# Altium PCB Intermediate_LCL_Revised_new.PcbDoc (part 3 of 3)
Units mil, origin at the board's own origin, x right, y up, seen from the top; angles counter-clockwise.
Board outline 12850 x 6950 mil, 4 copper layers (Top Layer, Lay1, gnd, Bottom Layer), stack 23.756 mil thick; 473 components, 243 nets, 1278 pads, 73 vias.
Unrouted connection lines stored in the file: 289.
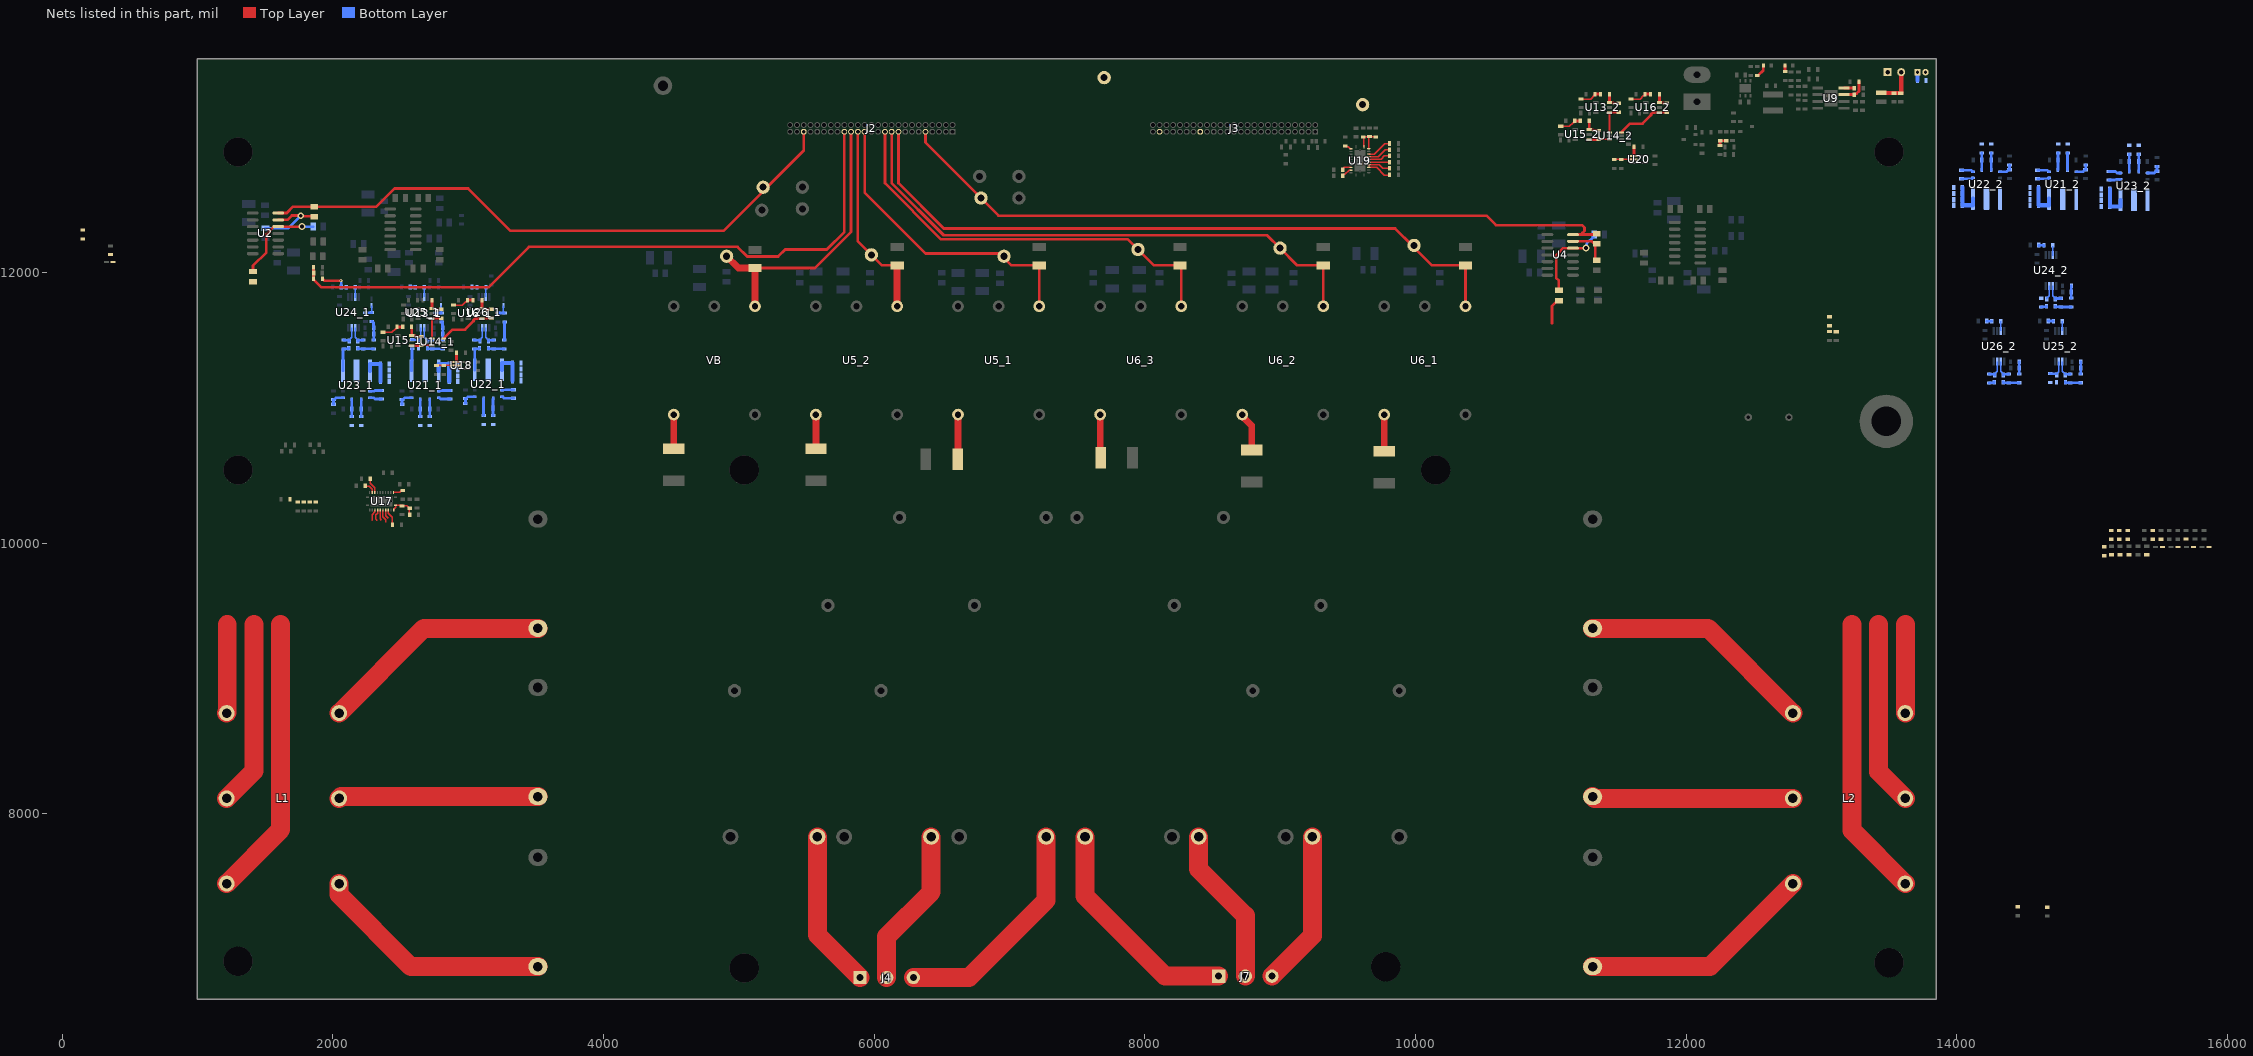
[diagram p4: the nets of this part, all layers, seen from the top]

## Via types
v1: diameter 50, hole 28, Top Layer to Bottom Layer, 40 vias
v2: diameter 20, hole 12, Top Layer to Bottom Layer, 29 vias
v3: diameter 40, hole 20, Top Layer to Bottom Layer, 4 vias

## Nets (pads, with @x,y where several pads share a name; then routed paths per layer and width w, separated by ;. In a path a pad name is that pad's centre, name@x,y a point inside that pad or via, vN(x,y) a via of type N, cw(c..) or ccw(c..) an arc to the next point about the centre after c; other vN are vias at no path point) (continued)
NetC56_2_1: C56_2.1 R57_2.1 R58_2.2 | length 162.2
  Top Layer w10: C56_2.1@11224,13281.21 11294.67,13281.21 11327,13313.54 R57_2.1@11327,13318.46
  Top Layer w20: R57_2.1@11327,13318.46 R58_2.2@11367.89,13318.46
NetC59_1_1: C59_1.1 R60_1.1 R61_1.2 | length 162.7
  Top Layer w10: C59_1.1@2372.51,11558.99 2437,11558.99 2463.77,11585.76 2468.7,11585.76 2475.51,11592.57 R60_1.1@2475.51,11597.49
  Top Layer w20: R60_1.1@2475.51,11597.49 R61_1.2@2516.4,11597.49
NetC59_2_1: C59_2.1 R60_2.1 R61_2.2 | length 162.7
  Top Layer w10: C59_2.1@11074,13081.21 11138.49,13081.21 11165.26,13107.98 11170.19,13107.98 11177,13114.79 R60_2.1@11177,13119.71
  Top Layer w20: R60_2.1@11177,13119.71 R61_2.2@11217.89,13119.71
NetC61_1_1: C61_1.1 R63_1.1 R64_1.2 | length 162.2
  Top Layer w10: C61_1.1@2892.51,11758.99 2958.25,11758.99 2983.77,11784.51 2988.7,11784.51 2995.51,11791.32 R63_1.1@2995.51,11796.24
  Top Layer w20: R63_1.1@2995.51,11796.24 R64_1.2@3036.4,11796.24
NetC61_2_1: C61_2.1 R63_2.1 R64_2.2 | length 162.2
  Top Layer w10: C61_2.1@11594,13281.21 11659.74,13281.21 11685.26,13306.72 11690.19,13306.72 11697,13313.54 R63_2.1@11697,13318.46
  Top Layer w20: R63_2.1@11697,13318.46 R64_2.2@11737.89,13318.46
NetC63_1: C63.1 R66.1 R67.1 U17.23 U17.24 | length 203.7
  Top Layer w10: U17.23@2449.57,10244.53 2449.57,10251.06 2464.33,10265.83 U17.24@2464.33,10278.98 ; U17.24@2464.33,10279.96 2464.61,10279.68 2512.99,10279.68 2515.96,10276.72 2547.69,10276.72 2557.13,10267.28 2557.13,10264.4 2563.94,10257.59 R66.1@2568.86,10257.59 2565.29,10254.02 R67.1@2565.29,10211.4
NetC75_1: C75.1 R100.1 R101.1 U19.23 U19.24 | length 250.2
  Top Layer w10: R100.1@9615.24,13001.28 R100.1@9619.53,13001.28 ; U19.24@9619.53,12929.53 R100.1@9619.53,13001.28 ; U19.23@9654.96,12916.1 9654.96,12995.57 C75.1@9660.68,13001.28 ; R101.1@9706.15,13001.28 C75.1@9660.68,13001.28 ; R100.1@9619.53,13001.28 C75.1@9660.68,13001.28
NetC88_1_2: C88_1.2 R124_1.1 U21_1.6 | length 110.7
  Bottom Layer w20: R124_1.1@2512.06,11026.24 C88_1.2@2512.06,11061.74 2518.95,11061.74 2532.49,11075.29 U21_1.6@2581.67,11075.29
NetC88_2_2: C88_2.2 R124_2.1 U21_2.6 | length 110.7
  Bottom Layer w20: U21_2.6@14883.49,12744.95 14932.66,12744.95 14946.2,12758.5 C88_2.2@14953.09,12758.5 R124_2.1@14953.09,12794
NetC89_1_1: C89_1.1 U21_1.2 | length 86.6
  Bottom Layer w20: U21_1.2@2782.45,11122.53 2786.08,11122.53 2791.05,11127.5 C89_1.1@2867.02,11127.5
NetC89_1_2: C89_1.2 U21_1.3 | length 89
  Bottom Layer w20: U21_1.3@2782.45,11075.29 2786.08,11075.29 2796.85,11064.51 C89_1.2@2867.02,11064.51
NetC89_2_1: C89_2.1 U21_2.2 | length 86.6
  Bottom Layer w20: C89_2.1@14598.13,12692.74 14674.11,12692.74 14679.08,12697.71 U21_2.2@14682.7,12697.71
NetC89_2_2: C89_2.2 U21_2.3 | length 89
  Bottom Layer w20: C89_2.2@14598.13,12755.73 14668.3,12755.73 14679.08,12744.95 U21_2.3@14682.7,12744.95
NetC90_1_1: C90_1.1 R125_1.1 U21_1.4 | length 127.5
  Bottom Layer w20: R125_1.1@2716.39,10936.39 2716.39,11058.75 2717.49,11059.85 U21_1.4@2717.49,11063.48
NetC90_2_1: C90_2.1 R125_2.1 U21_2.4 | length 127.5
  Bottom Layer w20: U21_2.4@14747.66,12756.76 14747.66,12760.39 14748.77,12761.49 R125_2.1@14748.77,12883.85
NetC91_1_1: C91_1.1 R126_1.1 U21_1.5 | length 127.3
  Bottom Layer w20: R126_1.1@2646.17,10936.39 2646.17,11059.39 2646.63,11059.85 U21_1.5@2646.63,11063.48
NetC91_2_1: C91_2.1 R126_2.1 U21_2.5 | length 127.3
  Bottom Layer w20: U21_2.5@14818.53,12756.76 14818.53,12760.39 14818.99,12760.85 R126_2.1@14818.99,12883.85
NetC96_1_2: C96_1.2 R127_1.1 U22_1.6 | length 110.7
  Bottom Layer w20: R127_1.1@2980,11032.92 C96_1.2@2980,11068.43 2986.89,11068.43 3000.43,11081.97 U22_1.6@3049.61,11081.97
NetC96_2_2: C96_2.2 R127_2.1 U22_2.6 | length 110.7
  Bottom Layer w20: U22_2.6@14320.39,12744.95 14369.57,12744.95 14383.11,12758.5 C96_2.2@14390,12758.5 R127_2.1@14390,12794
NetC97_1_1: C97_1.1 U22_1.2 | length 86.6
  Bottom Layer w20: U22_1.2@3250.39,11129.21 3254.02,11129.21 3258.99,11134.18 C97_1.1@3334.96,11134.18
NetC97_1_2: C97_1.2 U22_1.3 | length 89
  Bottom Layer w20: U22_1.3@3250.39,11081.97 3254.02,11081.97 3264.79,11071.19 C97_1.2@3334.96,11071.19
NetC97_2_1: C97_2.1 U22_2.2 | length 86.6
  Bottom Layer w20: C97_2.1@14035.04,12692.74 14111.01,12692.74 14115.98,12697.71 U22_2.2@14119.61,12697.71
NetC97_2_2: C97_2.2 U22_2.3 | length 89
  Bottom Layer w20: C97_2.2@14035.04,12755.73 14105.21,12755.73 14115.98,12744.95 U22_2.3@14119.61,12744.95
NetC98_1_1: C98_1.1 R128_1.1 U22_1.4 | length 127.5
  Bottom Layer w20: R128_1.1@3184.32,10943.07 3184.32,11065.43 3185.43,11066.54 U22_1.4@3185.43,11070.16
NetC98_2_1: C98_2.1 R128_2.1 U22_2.4 | length 127.5
  Bottom Layer w20: U22_2.4@14184.57,12756.76 14184.57,12760.39 14185.68,12761.49 R128_2.1@14185.68,12883.85
NetC99_1_1: C99_1.1 R129_1.1 U22_1.5 | length 127.3
  Bottom Layer w20: R129_1.1@3114.11,10943.07 3114.11,11066.07 3114.57,11066.54 U22_1.5@3114.57,11070.16
NetC99_2_1: C99_2.1 R129_2.1 U22_2.5 | length 127.3
  Bottom Layer w20: U22_2.5@14255.43,12756.76 14255.43,12760.39 14255.89,12760.85 R129_2.1@14255.89,12883.85
NetC104_1_2: C104_1.2 R130_1.1 U23_1.6 | length 110.7
  Bottom Layer w20: R130_1.1@2005.15,11026.24 C104_1.2@2005.15,11061.74 2012.04,11061.74 2025.59,11075.29 U23_1.6@2074.76,11075.29
NetC104_2_2: C104_2.2 R130_2.1 U23_2.6 | length 110.7
  Bottom Layer w20: U23_2.6@15410.39,12734.95 15459.57,12734.95 15473.11,12748.5 C104_2.2@15480,12748.5 R130_2.1@15480,12784
NetC105_1_1: C105_1.1 U23_1.2 | length 86.6
  Bottom Layer w20: U23_1.2@2275.55,11122.53 2275.7,11122.69 2306.6,11122.69 2311.41,11127.5 C105_1.1@2360.12,11127.5
NetC105_1_2: C105_1.2 U23_1.3 | length 89
  Bottom Layer w20: U23_1.3@2275.55,11075.29 2275.7,11075.13 2300.79,11075.13 2311.41,11064.51 C105_1.2@2360.12,11064.51
NetC105_2_1: C105_2.1 U23_2.2 | length 86.6
  Bottom Layer w20: C105_2.1@15125.04,12682.74 15173.74,12682.74 15178.55,12687.55 15209.45,12687.55 U23_2.2@15209.61,12687.71
NetC105_2_2: C105_2.2 U23_2.3 | length 89
  Bottom Layer w20: C105_2.2@15125.04,12745.73 15173.74,12745.73 15184.36,12735.11 15209.45,12735.11 U23_2.3@15209.61,12734.95
NetC106_1_1: C106_1.1 R131_1.1 U23_1.4 | length 127.5
  Bottom Layer w20: R131_1.1@2209.48,10936.39 2210.43,10937.34 2210.43,11063.32 U23_1.4@2210.59,11063.48
NetC106_2_1: C106_2.1 R131_2.1 U23_2.4 | length 127.5
  Bottom Layer w20: U23_2.4@15274.57,12746.76 15274.72,12746.92 15274.72,12872.9 R131_2.1@15275.68,12873.85
NetC107_1_1: C107_1.1 R132_1.1 U23_1.5 | length 127.3
  Bottom Layer w20: R132_1.1@2139.26,10936.39 2139.56,10936.69 2139.56,11063.32 U23_1.5@2139.72,11063.48
NetC107_2_1: C107_2.1 R132_2.1 U23_2.5 | length 127.3
  Bottom Layer w20: U23_2.5@15345.43,12746.76 15345.59,12746.92 15345.59,12873.55 R132_2.1@15345.89,12873.85
NetC109_1_1: C109_1.1 R136_1.2 U24_1.2 | length 144.7
  Bottom Layer w10: U24_1.2@2165.8,11591.65 2165.8,11519.63 C109_1.1@2184.5,11500.93
  Bottom Layer w20: C109_1.1@2184.5,11494.04 2184.5,11497.61 2186.31,11499.42 2223.83,11499.42 R136_1.2@2225.64,11501.24
NetC109_1_2: C109_1.2 R135_1.2 U24_1.3 | length 144.3
  Bottom Layer w10: C109_1.2@2121.5,11500.93 2140.2,11519.63 U24_1.3@2140.2,11591.65
  Bottom Layer w20: R135_1.2@2080.45,11500.93 2082.26,11499.11 2119.69,11499.11 2121.5,11497.3 C109_1.2@2121.5,11494.04
NetC109_2_1: C109_2.1 R136_2.2 U24_2.2 | length 144.7
  Bottom Layer w10: U24_2.2@14710.03,11900.72 14710.03,11828.7 C109_2.1@14728.73,11810
  Bottom Layer w20: C109_2.1@14728.73,11803.11 14728.73,11806.69 14730.54,11808.5 14768.06,11808.5 R136_2.2@14769.87,11810.31
NetC109_2_2: C109_2.2 R135_2.2 U24_2.3 | length 105.4
  Bottom Layer w10: C109_2.2@14665.74,11803.11 14665.74,11810 14684.44,11828.7 U24_2.3@14684.44,11900.72
NetC113_1_1: C113_1.1 R142_1.2 U25_1.2 | length 143.8
  Bottom Layer w10: U25_1.2@2675.8,11591.65 2675.8,11522.4 2697.26,11500.93 C113_1.1@2697.26,11494.04
  Bottom Layer w20: C113_1.1@2699.08,11499.42 2733.83,11499.42 R142_1.2@2735.64,11501.24
NetC113_1_2: C113_1.2 R141_1.2 U25_1.3 | length 151.7
  Bottom Layer w10: C113_1.2@2634.27,11494.04 2634.27,11500.93 2650.2,11516.86 U25_1.3@2650.2,11591.65
  Bottom Layer w20: R141_1.2@2585.77,11503.93 2587.58,11502.11 C113_1.2@2632.46,11502.11
NetC113_2_1: C113_2.1 R142_2.2 U25_2.2 | length 143.8
  Bottom Layer w10: U25_2.2@14780.03,11340.72 14780.03,11271.47 14801.5,11250 C113_2.1@14801.5,11243.11
  Bottom Layer w20: C113_2.1@14803.31,11248.5 14838.06,11248.5 R142_2.2@14839.87,11250.31
NetC113_2_2: C113_2.2 R141_2.2 U25_2.3 | length 151.7
  Bottom Layer w10: C113_2.2@14738.5,11243.11 14738.5,11250 14754.44,11265.93 U25_2.3@14754.44,11340.72
  Bottom Layer w20: R141_2.2@14690,11253 14691.81,11251.19 C113_2.2@14736.69,11251.19
NetC117_1_1: C117_1.1 R148_1.2 U26_1.2 | length 144.7
  Bottom Layer w10: U26_1.2@3131.12,11591.65 3131.12,11519.63 C117_1.1@3149.82,11500.93
  Bottom Layer w20: C117_1.1@3149.82,11494.04 3149.82,11497.61 3151.63,11499.42 3189.15,11499.42 R148_1.2@3190.96,11501.24
NetC117_1_2: C117_1.2 R147_1.2 U26_1.3 | length 144.3
  Bottom Layer w10: C117_1.2@3086.82,11500.93 3105.53,11519.63 U26_1.3@3105.53,11591.65
  Bottom Layer w20: R147_1.2@3045.77,11500.93 3047.58,11499.11 3085.01,11499.11 3086.82,11497.3 C117_1.2@3086.82,11494.04
NetC117_2_1: C117_2.1 R148_2.2 U26_2.2 | length 144.7
  Bottom Layer w10: U26_2.2@14325.35,11340.72 14325.35,11268.7 C117_2.1@14344.05,11250
  Bottom Layer w20: C117_2.1@14344.05,11243.11 14344.05,11246.69 14345.86,11248.5 14383.38,11248.5 R148_2.2@14385.19,11250.31
NetC117_2_2: C117_2.2 R147_2.2 U26_2.3 | length 144.3
  Bottom Layer w10: C117_2.2@14281.06,11250 14299.76,11268.7 U26_2.3@14299.76,11340.72
  Bottom Layer w20: R147_2.2@14240,11250 14241.81,11248.19 14279.24,11248.19 14281.06,11246.38 C117_2.2@14281.06,11243.11
NetDS1_1: DS1.1 R29.1 | length 45
  Top Layer w20: R29.1@12731.2,13485.15 12731.33,13485.28 12731.33,13529.87 DS1.1@12731.46,13530
NetDS2_1: DS2.1 R43.1 | length 96.2
  Top Layer w20: R43.1@12527.45,13455.58 12532.37,13455.58 12571.15,13494.35 12571.15,13528.19 DS2.1@12572.96,13530
NetR2_2: R2.2 R4.2 U2.6 | length 581.1
  Top Layer w20: U2.6@1597.09,12388.86 1665.18,12388.86 1697.3,12420.98 1760.48,12420.98 1766.3,12415.16 1858.9,12415.16 R2.2@1862.6,12411.46
  Bottom Layer w20: R4.2@1502.6,12326.26 1670,12326.26 v1(1762.6,12418.86)
NetR5_2: R5.2 R6.1 U2.5 | length 700.5
  Top Layer w20: R5.2@1410,12000.56 1410,12050 1508.84,12148.84 1508.84,12282.11 1565.59,12338.86 U2.5@1597.09,12338.86 v1(1772.6,12338.86)
  Bottom Layer w20: v1@1772.6,12346.98 v1(1772.6,12338.86) R6.1@1855.2,12338.86
NetR8_2: R8.2 R10.2 U4.6 | length 300.2
  Top Layer w20: U4.6@11164.49,12230 11303.74,12230 11321.14,12212.6 11330,12212.6 11330,12090 R10.2@11326.54,12093.46
NetR11_2: R11.2 R12.1 U4.5 | length 636.8
  Top Layer w20: R11.2@11060,11867.4 11060,11940.56 11040,11960.56 11040,12125.58 11068.82,12154.4 11068.82,12157.64 11091.18,12180 v1(11260,12180)
  Bottom Layer w20: v1(11260,12180) 11265.74,12185.74 11265.74,12214.28 11322.6,12271.14 R12.1@11322.6,12280
NetR13_1_2: R13_1.2 U5_1.5 | length 330.8
  Top Layer w50: R13_1.2@6618.11,10620 6619.06,10620.94 6619.06,10949.06 U5_1.5@6620,10950
NetR13_2_2: R13_2.2 U5_2.5 | length 231.9
  Top Layer w50: R13_2.2@5570,10718.11 U5_2.5@5570,10950
NetR13_3_2: R13_3.2 VB.5 | length 247.2
  Top Layer w50: R13_3.2@4520,10702.76 VB.5@4520,10950
NetR15_1_2: R15_1.2 U6_1.5 | length 271.9
  Top Layer w50: R15_1.2@9770,10678.11 U6_1.5@9770,10950
NetR15_2_2: R15_2.2 U6_2.5 | length 290.9
  Top Layer w50: U6_2.5@8720,10950 8720,10940.09 8790,10870.09 R15_2.2@8790,10688.11
NetR15_3_2: R15_3.2 U6_3.5 | length 321.6
  Top Layer w50: U6_3.5@7670,10950 7671.89,10948.11 7671.89,10631.89 R15_3.2@7673.78,10630
NetR34_2: R34.2 U9.4 | length 77
  Top Layer w20: U9.4@13167,13364 13239.44,13364 13241.65,13361.79 R34.2@13243.11,13361.79
NetR36_2: R36.2 R38.2 U9.3 | length 195.9
  Top Layer w20: U9.3@13167,13314 13167.5,13314.5 13242.83,13314.5 R36.2@13243.41,13315.08 13243.41,13320 13245.22,13321.81 13259.95,13321.81 13277.3,13339.15 13277.3,13410.35 R38.2@13278.08,13411.14
NetR58_1_1: R58_1.1 R59_1.2 U13_1.3 | length 134.4
  Top Layer w20: R58_1.1@2732.4,11796.24 2732.45,11796.19 U13_1.3@2732.51,11734.89 U13_1.3@2732.51,11734.89 2734.32,11733.08 2756.7,11733.08 2761.78,11728 R59_1.2@2802.67,11728
NetR58_2_1: R58_2.1 R59_2.2 U13_2.3 | length 134.4
  Top Layer w20: R58_2.1@11433.89,13318.46 11433.94,13318.4 11433.94,13257.16 U13_2.3@11434,13257.11 11435.81,13255.3 11458.19,13255.3 11463.27,13250.22 R59_2.2@11504.16,13250.22
NetR59_1_1: R59_1.1 U13_1.1 U14_1.1 | length 217.5
  Top Layer w10: U14_1.1@2733.46,11513.65 U14_1.1@2733.81,11513.31 ; R59_1.1@2801.72,11661.05 R59_1.1@2802.67,11662
  Top Layer w15: U14_1.1@2733.46,11513.65 U13_1.1@2733.46,11661.05
  Top Layer w20: U13_1.1@2733.46,11661.05 R59_1.1@2801.72,11661.05
NetR59_2_1: R59_2.1 U13_2.1 U14_2.1 | length 217.5
  Top Layer w10: U14_2.1@11434.95,13035.87 U14_2.1@11435.3,13035.52 ; R59_2.1@11503.21,13183.26 R59_2.1@11504.16,13184.22
  Top Layer w15: U14_2.1@11434.95,13035.87 U13_2.1@11434.95,13183.26
  Top Layer w20: U13_2.1@11434.95,13183.26 R59_2.1@11503.21,13183.26
NetR61_1_1: R61_1.1 R62_1.2 U15_1.3 | length 135.7
  Top Layer w20: R61_1.1@2582.4,11597.49 2582.45,11597.44 U15_1.3@2582.51,11534.89 U15_1.3@2582.51,11534.89 2584.32,11533.08 2606.7,11533.08 2611.77,11528.01 R62_1.2@2652.67,11528.01
NetR61_2_1: R61_2.1 R62_2.2 U15_2.3 | length 135.7
  Top Layer w20: R61_2.1@11283.89,13119.71 R61_2.1@11283.89,13119.71 11283.94,13057.16 U15_2.3@11284,13057.11 11285.81,13055.3 11308.19,13055.3 11313.26,13050.22 R62_2.2@11354.16,13050.22
NetR62_1_1: R62_1.1 U14_1.3 U15_1.1 | length 152.1
  Top Layer w10: R62_1.1@2652.67,11462.01 2652.73,11462.07 U14_1.3@2733.81,11462.13 U14_1.3@2733.81,11462.13
  Top Layer w20: U15_1.1@2582.51,11461.05 R62_1.1@2645.84,11461.05 ; R62_1.1@2645.84,11460.09 2647.75,11462.01 R62_1.1@2652.67,11462.01
NetR62_2_1: R62_2.1 U14_2.3 U15_2.1 | length 152.1
  Top Layer w10: R62_2.1@11354.16,12984.22 11354.22,12984.28 11435.24,12984.28 U14_2.3@11435.3,12984.34
  Top Layer w20: U15_2.1@11284,12983.26 R62_2.1@11347.33,12983.26 ; R62_2.1@11347.33,12982.31 11349.24,12984.22 R62_2.1@11354.16,12984.22
NetR64_1_1: R64_1.1 R65_1.2 U16_1.3 | length 134.4
  Top Layer w20: R64_1.1@3102.4,11796.24 3102.45,11796.19 U16_1.3@3102.51,11734.89 U16_1.3@3102.51,11734.89 3104.32,11733.08 3126.7,11733.08 3131.78,11728 R65_1.2@3172.67,11728
NetR64_2_1: R64_2.1 R65_2.2 U16_2.3 | length 116.9
  Top Layer w20: R64_2.1@11803.89,13318.46 11803.94,13318.4 11803.94,13257.16 U16_2.3@11804,13257.11 11805.81,13255.3 11828.19,13255.3 11833.27,13250.22 R65_2.2@11856.67,13250.22
NetR65_1_1: R65_1.1 U14_1.6 U16_1.1 | length 414.8
  Top Layer w20: U14_1.6@2822.71,11515.59 2884.91,11577.79 2977.62,11577.79 3039.82,11640 3039.82,11647.09 3052.82,11660.09 U16_1.1@3102.51,11660.09 ; U16_1.1@3102.51,11661.05 R65_1.1@3165.84,11661.05 ; R65_1.1@3165.84,11660.09 3167.75,11662 R65_1.1@3172.67,11662
NetR65_2_1: R65_2.1 U14_2.6 U16_2.1 | length 401.3
  Top Layer w20: U14_2.6@11524.2,13037.81 11586.4,13100.01 11679.11,13100.01 11741.31,13162.21 11741.31,13169.31 11754.31,13182.31 U16_2.1@11804,13182.31 ; U16_2.1@11804,13183.26 R65_2.1@11861.48,13183.26
NetR70_2: R70.2 U17.2 | length 73.8
  Top Layer w10: U17.2@2448.58,10374.45 2495.62,10374.45 2511.04,10389.86 R70.2@2515.96,10389.86
NetR90_1: R90.1 U17.9 | length 114.5
  Top Layer w10: R90.1@2277.26,10475.08 2277.26,10442.74 2310.79,10409.21 U17.9@2310.79,10374.45
NetR91_1: R91.1 U17.10 | length 86.7
  Top Layer w10: R91.1@2239.97,10425.73 2245.7,10420 2270,10420 2291.1,10398.9 U17.10@2291.1,10374.45
NetR93_2: R93.2 R94.2 U18.2 | length 147.9
  Top Layer w10: R93.2@2767.19,11314.33 2767.95,11313.57 R94.2@2820.42,11313.57 ; R94.2@2820.48,11312.91 2820.42,11312.96 R94.2@2820.42,11313.57 ; U18.2@2914.05,11313.57 R94.2@2820.42,11313.57
NetR105_2: R105.2 U19.2 | length 52.7
  Top Layer w10: R105.2@9481.25,12935.24 9488.06,12928.43 9503.85,12928.43 9518.5,12913.78 U19.2@9525.04,12913.78
NetR119_1: R119.1 U19.9 | length 71.5
  Top Layer w10: R119.1@9463,12760 9463,12764.92 9474.06,12775.98 U19.9@9525.04,12775.98
NetR120_1: R120.1 U19.10 | length 82.7
  Top Layer w10: R120.1@9463,12713.5 9463,12718.42 9469.81,12725.23 9478.67,12725.23 9509.47,12756.02 9524.76,12756.02 U19.10@9525.04,12756.3
NetR122_2: R122.2 R123.2 U20.2 | length 147.9
  Top Layer w10: R122.2@11468.58,12835.79 U20.2@11615.54,12835.79
  Top Layer w20: R122.2@11467.92,12835.12 R122.2@11468.58,12835.79
NetR138_1_2: R138_1.2 U24_1.7 | length 71.6
  Bottom Layer w10: U24_1.7@2165.8,11814.49 2165.9,11814.59 2165.9,11885.89 R138_1.2@2166,11885.99
NetR138_2_2: R138_2.2 U24_2.7 | length 71.6
  Bottom Layer w10: U24_2.7@14710.03,12123.56 14710.13,12123.67 14710.13,12194.96 R138_2.2@14710.23,12195.06
NetR144_1_2: R144_1.2 U25_1.7 | length 71.6
  Bottom Layer w10: U25_1.7@2675.8,11820 2675.9,11820.1 2675.9,11891.39 R144_1.2@2676,11891.5
NetR144_2_2: R144_2.2 U25_2.7 | length 71.6
  Bottom Layer w10: U25_2.7@14780.03,11569.07 14780.13,11569.17 14780.13,11640.47 R144_2.2@14780.23,11640.57
NetR150_1_2: R150_1.2 U26_1.7 | length 71.6
  Bottom Layer w10: U26_1.7@3131.12,11820 3131.22,11820.1 3131.22,11891.39 R150_1.2@3131.32,11891.5
NetR150_2_2: R150_2.2 U26_2.7 | length 71.6
  Bottom Layer w10: U26_2.7@14325.35,11569.07 14325.45,11569.17 14325.45,11640.47 R150_2.2@14325.55,11640.57
PGND: C53.2 C54.1 C84_1.1 C84_2.1 C85_1.2 C85_2.2 C86_1.1 C86_2.1 C87_1.1 C87_2.1 C92_1.1 C92_2.1 C93_1.2 C93_2.2 C94_1.1 C94_2.1 C95_1.1 C95_2.1 C100_1.1 C100_2.1 C101_1.2 C101_2.2 C102_1.1 C102_2.1 C103_1.1 C103_2.1 P1.1 R55.2 R56.2 U21_1.9 U21_2.9 U22_1.9 U22_2.9 U23_1.9 U23_2.9
Ph-A1: R133_1.2 R135_1.1 U23_1.8 | length 208.7
  Bottom Layer w20: U23_1.8@2074.76,11273.32 2074.76,11433.11 2076.57,11434.93 R135_1.1@2080.45,11434.93 2082.26,11436.74 2116.69,11436.74 2118.5,11438.55 R133_1.2@2118.5,11441.5
Ph-A2: R133_2.2 R135_2.1 U23_2.8 | length 42.5
  Bottom Layer w20: R135_2.1@14624.68,11744 14626.49,11745.81 14660.92,11745.81 14662.73,11747.62 R133_2.2@14662.73,11750.57
Ph-B1: R139_1.2 R141_1.1 U21_1.8 | length 166.3
  Bottom Layer w20: U21_1.8@2581.67,11273.32 2581.67,11343.2 2585.77,11347.3 R141_1.1@2585.77,11437.93
Ph-B2: R139_2.2 R141_2.1 U21_2.8
Ph-C1: R145_1.2 R147_1.1 U22_1.8 | length 197.6
  Bottom Layer w20: R147_1.1@3045.77,11434.93 3047.8,11434.93 3049.61,11433.11 U22_1.8@3049.61,11280 ; R147_1.1@3047.58,11436.74 3082.01,11436.74 3083.82,11438.55 R145_1.2@3083.82,11441.5
Ph-C2: R145_2.2 R147_2.1 U22_2.8 | length 42.5
  Bottom Layer w20: R147_2.1@14240,11184 14241.81,11185.81 14276.24,11185.81 14278.05,11187.62 R145_2.2@14278.05,11190.57
PWM_AH1: R107.1 R131_1.2 U19.21 | length 185.9
  Top Layer w10: U19.21@9654.96,12875.39 9695.39,12875.39 9773.11,12953.11 R107.1@9808.68,12953.11
PWM_AH2: R78.1 R131_2.2 U17.21 | length 121.5
  Top Layer w10: U17.21@2410.2,10244.53 2410.2,10220.2 2438.7,10191.69 R78.1@2438.7,10134.8
PWM_AL1: R108.1 R132_1.2 U19.20 | length 175
  Top Layer w10: U19.20@9654.96,12855.71 9725.71,12855.71 9777.11,12907.11 R108.1@9808.68,12907.11
PWM_AL2: R79.1 R132_2.2 U17.20 | length 70.1
  Top Layer w10: U17.20@2390.51,10244.53 2390.51,10204.22 2411.58,10183.15
PWM_BH1: R109.1 R125_1.2 U19.19 | length 164.1
  Top Layer w10: U19.19@9654.96,12836.02 9746.02,12836.02 9771.11,12861.11 R109.1@9808.68,12861.11
PWM_BH2: R80.1 R125_2.2 U17.19 | length 98
  Top Layer w10: U17.19@2370.83,10244.53 2370.83,10193.23 2390.7,10173.36 2390.7,10154.72
PWM_BL1: R110.1 R126_1.2 U19.18 | length 154.2
  Top Layer w10: U19.18@9654.96,12816.34 9807.45,12816.34 R110.1@9808.68,12815.11
PWM_BL2: R81.1 R126_2.2 U17.18 | length 79.7
  Top Layer w10: U17.18@2351.14,10244.53 2351.14,10179.16 2359.35,10170.96 2359.35,10168.25
PWM_CH1: R111.1 R128_1.2 U19.17 | length 165.1
  Top Layer w10: U19.17@9654.96,12796.65 9733.35,12796.65 9760,12770 9807.79,12770 R111.1@9808.68,12769.11
PWM_CH2: R82.1 R128_2.2 U17.17 | length 85.8
  Top Layer w10: 2325.67,10166.41 2325.67,10168.7 2325.67,10171.41 2319.25,10177.83 2319.25,10209.25 2331.46,10221.46 U17.17@2331.46,10244.53
PWM_CL1: R112.1 R129_1.2 U19.16 | length 178.6
  Top Layer w10: U19.16@9654.96,12776.97 9713.03,12776.97 9770,12720 9805.57,12720 R112.1@9808.68,12723.11
PWM_CL2: R83.1 R129_2.2 U17.16 | length 85.3
  Top Layer w10: 2288.87,10168.7 2290,10169.83 2290,10211.02 2311.77,10232.79 U17.16@2311.77,10244.53
PWM_EN_1: J3.35 R92.2 TP12.1 U18.1 | length 65
  Top Layer w20: R92.2@2914,11406.78 2914,11341.81 U18.1@2914.05,11341.76
PWM_EN_2: J3.47 R121.2 TP18.1 U20.1 | length 65.2
  Top Layer w20: U20.1@11615.54,12863.97 11615.89,12864.32 R121.2@11615.89,12929
V_capA_1: J2.27 R14_1.2 TP8.1 U5_1.2 | length 2265.5
  Top Layer w20: J2.27@5930,13040 5930,12590 6380,12140 6924.1,12140 6949.1,12115 6955,12115 7016.93,12053.07 R14_1.2@7220,12053.07 U5_1.2@7220,11750
V_capA_2: J2.29 R14_2.2 TP9.1 U5_2.2 | length 1476.4
  Top Layer w20: J2.29@5880,13040 5880,12230 TP9.1@5980,12130 6056.93,12053.07 R14_2.2@6170,12053.07
  Top Layer w50: U5_2.2@6170,11750 R14_2.2@6170,12053.07
V_capA_3: J2.31 R14_3.2 TP10.1 VB.2 | length 2089.6
  Top Layer w20: R14_3.2@5120,12033.07 5563.07,12033.07 5830,12300 J2.31@5830,13040
  Top Layer w50: TP10.1@4910,12120 4996.93,12033.07 R14_3.2@5120,12033.07 VB.2@5120,11750
V_capB_1: J2.17 R16_1.2 TP5.1 U6_1.2 | length 5124.5
  Top Layer w20: J2.17@6180,13040 6180,12660 6514.46,12325.54 9850,12325.54 9977.77,12197.77 10007.77,12167.77 10122.47,12053.07 R16_1.2@10370,12053.07 U6_1.2@10370,11750
V_capB_2: J2.19 R16_2.2 TP6.1 U6_2.2 | length 4124.5
  Top Layer w20: J2.19@6130,13040 6130,12660 6514.79,12275.21 8904.79,12275.21 TP6.1@9000,12180 9126.93,12053.07 R16_2.2@9320,12053.07 U6_2.2@9320,11750
V_capB_3: J2.21 R16_3.2 TP7.1 U6_3.2 | length 3110.1
  Top Layer w20: J2.21@6080,13040 6080,12660 6494.79,12245.21 7874.79,12245.21 TP7.1@7950,12170 8066.93,12053.07 R16_3.2@8260,12053.07 ; U6_3.2@8270,11750 R16_3.2@8270,12043.07
  Bottom Layer w50: U6_3.2@8266.01,11753.99 U6_3.2@8270,11750
V_o_outA_1: J4.3 L4_1.2 | length 1686.6
  Top Layer w140: J4.3@6290,6790 6700,6790 7271.26,7361.26 L4_1.2@7271.26,7830
V_o_outA_2: J4.2 L4_2.2 | length 1175.9
  Top Layer w140: J4.2@6093.15,6790 6093.15,7093.15 6421.26,7421.26 L4_2.2@6421.26,7830
V_o_outA_3: J4.1 L4_3.2 | length 1170.5
  Top Layer w140: L4_3.2@5581.26,7830 5581.26,7105.04 J4.1@5896.3,6790
V_o_outB_1: J7.3 L6_1.2 | length 1153.7
  Top Layer w140: J7.3@8940,6800 9238.74,7098.74 L6_1.2@9238.74,7830
V_o_outB_2: J7.2 L6_2.2 | length 1172.7
  Top Layer w140: L6_2.2@8398.74,7830 8398.74,7591.26 8743.15,7246.85 J7.2@8743.15,6800
V_o_outB_3: J7.1 L6_3.2 | length 1671.2
  Top Layer w140: L6_3.2@7558.74,7830 7558.74,7391.26 8150,6800 J7.1@8546.3,6800
V_termA_1: L1.4 L3_1.1 | length 1728.8
  Top Layer w140: L1.4@2046.42,8744.31 2672.95,9370.84 L3_1.1@3515.71,9370.84
V_termA_2: L1.5 L3_2.1 | length 1474.6
  Top Layer w140: L1.5@2046.42,8114.39 2059.33,8127.3 L3_2.1@3515.71,8127.3
V_termA_3: L1.6 L3_3.1 | length 1771.8
  Top Layer w140: L1.6@2046.42,7484.46 2046.42,7402.02 2577.6,6870.84 L3_3.1@3515.71,6870.84
V_termB_1: L2.4 L5_1.1 | length 1733.5
  Top Layer w140: L5_1.1@11310,6870.46 12175.67,6870.46 L2.4@12789.29,7484.08
V_termB_2: L2.5 L5_2.1 | length 1484.5
  Top Layer w140: L5_2.1@11310,8126.46 11322.46,8114 L2.5@12789.29,8114
V_termB_3: L2.6 L5_3.1 | length 1738.8
  Top Layer w140: L5_3.1@11310,9370.46 12162.76,9370.46 L2.6@12789.29,8743.92
VA1: C108_1.1 R69.1 R134_1.1 R137_1.2 | length 146
  Bottom Layer w20: R69.1@2287.01,11637.4 2291.93,11637.4 2301.19,11628.15 2301.19,11593.31 R137_1.2@2303,11591.5 2303,11546.08 2303,11503.51 2301.19,11501.7 R134_1.1@2301.11,11501.7
VA2: C108_2.1 R96.1 R134_2.1 R137_2.2 | length 90.6
  Bottom Layer w20: R134_2.1@14845.34,11810.77 14845.42,11810.77 14847.23,11812.58 R137_2.2@14847.23,11900.57
VA11: C69.1 D3.2 R69.2 | length 98.9
  Bottom Layer w10: R69.2@2287.01,11703.4 2289.1,11705.49 2289.1,11752.91 D3.2@2287.01,11755
  Bottom Layer w20: C69.1@2242.66,11700.4 2244.17,11701.9 2285.51,11701.9 R69.2@2287.01,11703.4
VA22: C80.1 D7.2 R96.2
VA-Motor1: L1.1 | length 657.9
  Top Layer w140: L1.1@1215.71,8743.92 1220,8748.21 1220,9400
VA-Motor2: L2.1 | length 2079
  Top Layer w140: 13226.3,9400 13226.3,7877.78 L2.1@13620,7484.08
VA_Motor1: R133_1.1 R134_1.2 R136_1.1 | length 120.9
  Bottom Layer w20: R133_1.1@2184.5,11441.5 2184.5,11438.86 2186.31,11437.05 2223.83,11437.05 R136_1.1@2225.64,11435.24 2225.87,11435.47 2300.88,11435.47 R134_1.2@2301.11,11435.7
VA_Motor2: R133_2.1 R134_2.2 R136_2.1 | length 120.9
  Bottom Layer w20: R133_2.1@14728.73,11750.57 14728.73,11747.93 14730.54,11746.12 14768.06,11746.12 R136_2.1@14769.87,11744.31 14770.1,11744.54 14845.11,11744.54 R134_2.2@14845.34,11744.77
VB1: C112_1.1 R71.1 R140_1.1 R143_1.2 | length 141
  Bottom Layer w20: R71.1@2803.49,11635.06 2808.42,11635.06 2811.19,11632.29 2811.19,11593.31 R143_1.2@2813,11591.5 2813,11503.51 2811.19,11501.7 R140_1.1@2811.11,11501.7
VB2: C112_2.1 R97.1 R140_2.1 R143_2.2 | length 90.6
  Bottom Layer w20: R140_2.1@14915.34,11250.77 14915.42,11250.77 14917.23,11252.58 R143_2.2@14917.23,11340.57
VB11: C66.1 D2.2 R71.2 | length 95.2
  Bottom Layer w10: R71.2@2800,11702.87 D2.2@2800,11755
  Bottom Layer w20: C66.1@2761.35,11698.85 2762.46,11699.96 2802.39,11699.96 R71.2@2803.49,11701.06
VB22: C77.1 D6.2 R97.2
VB-Motor1: L1.2 | length 1368.9
  Top Layer w140: L1.2@1215.71,8114.39 1416.85,8315.53 1416.85,9400
VB-Motor2: L2.2 | length 1367.5
  Top Layer w140: 13423.15,9400 13423.15,8310.85 L2.2@13620,8114
VB_Motor1: R139_1.1 R140_1.2 R142_1.1 | length 117.1
  Bottom Layer w20: R139_1.1@2698.77,11441.5 2698.77,11437.51 2700.58,11435.7 2735.64,11435.7 R140_1.2@2811.11,11435.7
VB_Motor2: R139_2.1 R140_2.2 R142_2.1 | length 117.1
  Bottom Layer w20: R139_2.1@14803,11190.57 14803,11186.58 14804.81,11184.77 R140_2.2@14915.34,11184.77
VBUS: C44.1 C45.1 C53.1 C54.2 C84_1.2 C84_2.2 C85_1.1 C85_2.1 C86_1.2 C86_2.2 C87_1.2 C87_2.2 C92_1.2 C92_2.2 C93_1.1 C93_2.1 C94_1.2 C94_2.2 C95_1.2 C95_2.2 C100_1.2 C100_2.2 C101_1.1 C101_2.1 C102_1.2 C102_2.2 C103_1.2 C103_2.2 L8.1 P1.2 R32.2 U21_1.1 U21_2.1 U22_1.1 U22_2.1 U23_1.1 U23_2.1 | length 1908.5
  Top Layer w30: L8.1@13441.76,13327.63 13443.1,13326.29 13588.15,13326.29 13590,13328.14 P1.2@13590,13480
  Bottom Layer w30: U23_1.1@2275.55,11273.32 2275.55,11322.02 2276.77,11323.24 C100_1.2@2353.66,11323.24 C101_1.1@2353.66,11279.91 C102_1.2@2353.66,11236.57 C103_1.2@2353.66,11193.24 ; U21_1.1@2782.45,11273.32 2782.45,11322.02 2783.67,11323.24 C84_1.2@2860.56,11323.24 C85_1.1@2860.56,11279.91 C86_1.2@2860.56,11236.57 C87_1.2@2860.56,11193.24 ; U22_1.1@3250.39,11280 3250.39,11328.7 3251.61,11329.92 C94_1.2@3328.5,11329.92 C95_1.2@3328.5,11286.59 C92_1.2@3328.5,11243.25 C93_1.1@3328.5,11199.92 ; C53.1@13710,13480 13710.33,13479.67 13710.33,13417.43 C54.2@13710.66,13417.1 ; C93_2.1@14041.5,12627 C92_2.2@14041.5,12583.67 C95_2.2@14041.5,12540.33 C94_2.2@14041.5,12497 14118.39,12497 14119.61,12498.22 U22_2.1@14119.61,12546.92 ; C87_2.2@14604.59,12627 C86_2.2@14604.59,12583.67 C85_2.1@14604.59,12540.33 C84_2.2@14604.59,12497 14681.48,12497 14682.7,12498.22 U21_2.1@14682.7,12546.92 ; C103_2.2@15131.5,12617 C102_2.2@15131.5,12573.67 C101_2.1@15131.5,12530.33 C100_2.2@15131.5,12487 15208.39,12487 15209.61,12488.22 U23_2.1@15209.61,12536.92
VC1: C116_1.1 R72.1 R146_1.1 R149_1.2 | length 134.9
  Bottom Layer w20: R146_1.1@3266.43,11501.7 3266.51,11501.7 3268.32,11503.51 R149_1.2@3268.32,11591.5 3269.16,11592.34 3269.16,11634.22 R72.1@3270,11635.06
VC2: C116_2.1 R98.1 R146_2.1 R149_2.2 | length 90.6
  Bottom Layer w20: R146_2.1@14460.66,11250.77 R146_2.1@14460.66,11250.77 14462.55,11252.58 R149_2.2@14462.55,11340.57
VC11: C70.1 D4.2 R72.2 | length 108
  Bottom Layer w10: D4.2@3260,11755 3260,11707.87 3266.81,11701.06 R72.2@3270,11701.06
  Bottom Layer w20: C70.1@3220,11698.05 3226.89,11698.05 3229.9,11701.06 R72.2@3266.81,11701.06
VC22: C81.1 D8.2 R98.2
VC-Motor1: L1.3 | length 2080.4
  Top Layer w140: L1.3@1215.71,7484.46 1613.7,7882.46 1613.7,9400
VC-Motor2: L2.3 | length 656.1
  Top Layer w140: L2.3@13620,8743.92 13620,9400
VC_Motor1: R145_1.1 R146_1.2 R148_1.1 | length 120.9
  Bottom Layer w20: R145_1.1@3149.82,11441.5 3149.82,11438.86 3151.63,11437.05 3189.15,11437.05 R148_1.1@3190.96,11435.24 3191.19,11435.47 3266.2,11435.47 R146_1.2@3266.43,11435.7
VC_Motor2: R145_2.1 R146_2.2 R148_2.1 | length 120.9
  Bottom Layer w20: R145_2.1@14344.05,11190.57 14344.05,11187.93 14345.86,11186.12 14383.38,11186.12 R148_2.1@14385.19,11184.31 14385.43,11184.54 14460.43,11184.54 R146_2.2@14460.66,11184.77
VDC: C43.1 R32.1 R35.2 R68.1 R95.1
VDCA_In: C65.1 D1.2 R5.1 R68.2
VDCA_Out: J2.45 R2.1 TP16.1 U2.7 | length 4471.4
  Top Layer w20: U2.7@1597.09,12438.86 1659.66,12438.86 1707.06,12486.26 R2.1@1862.6,12486.26 2321.56,12486.26 2455.3,12620 3000,12620 3310.79,12309.21 4889.21,12309.21 5480,12900 J2.45@5480,13040
VDCB_In: C76.1 D5.2 R11.1 R95.2 | length 193.5
  Top Layer w20: 11010,11625 11010,11751.46 11051.14,11792.6 R11.1@11060,11792.6
VDCB_Out: J2.09 R8.1 TP4.1 U4.7 | length 5428.2
  Top Layer w20: J2.09@6380,13040 6380,12960 TP4.1@6790,12550 6920,12420 10526.07,12420 10596.07,12350 11232.43,12350 11250,12332.43 11250,12307.57 11232.43,12290 ; U4.7@11164.49,12280 11165.18,12280.69 11232.43,12280.69 11323.29,12280.69 R8.1@11330,12287.4
VREF1: C110_1.1 C110_2.1 C114_1.1 C114_2.1 C118_1.1 C118_2.1 R25.1 R26.2 R27.2 R76.1 R138_1.1 R138_2.1 R144_1.1 R144_2.1 R150_1.1 R150_2.1 | length 501.8
  Top Layer w20: R76.1@1922.86,11954.49 1922.86,11949.57 1924.67,11947.76 1929.59,11947.76 1937.35,11940 v2(2060,11940) ; R27.2@12250.7,12937.25 12251.33,12937.87 12251.33,12972.77 R25.1@12251.95,12973.39 12252.26,12973.7 12295.24,12973.7 R26.2@12295.55,12974.01
  Bottom Layer w10: C118_1.1@3027.96,11893.46 C118_1.1@3029.93,11891.5 ; C118_2.1@14222.19,11642.54 C118_2.1@14224.16,11640.57
  Bottom Layer w20: v2(2060,11940) 2062.64,11937.36 C110_1.1@2062.64,11893.46 ; C110_1.1@2063.62,11891.5 R138_1.1@2099.02,11891.5 ; R138_1.1@2099.02,11886.97 R138_1.1@2100,11885.99 ; C114_1.1@2572.64,11893.46 2573.62,11892.48 2609.02,11892.48 R144_1.1@2610,11891.5 ; C118_1.1@3029.93,11891.5 R150_1.1@3065.32,11891.5 ; C118_2.1@14224.16,11640.57 R150_2.1@14259.55,11640.57 ; C110_2.1@14606.87,12197.03 C110_2.1@14607.85,12196.05 ; C110_2.1@14607.85,12200.57 R138_2.1@14643.25,12200.57 ; R138_2.1@14643.25,12196.05 R138_2.1@14644.23,12195.06 ; C114_2.1@14676.87,11642.54 14677.85,11641.55 14713.25,11641.55 R144_2.1@14714.23,11640.57
VREF2: R104.1
VREFA: C64.1 J2.33 R76.2 R77.1 | length 5009.2
  Top Layer w20: R77.1@1857,12040 1857.94,12039.06 1857.94,11998.68 C64.1@1858.88,11997.74 1857.87,11996.72 1857.87,11955.5 R76.2@1856.86,11954.49 1856.86,11949.57 1916.43,11890 3150,11890 3449.21,12189.21 4990.69,12189.21 5062.5,12117.4 5291.04,12117.4 5343.64,12170 5650,12170 5780,12300 J2.33@5780,13040
VREFB: C74.1 R104.2 R106.1
pads on no net: J3.25 J3.27 J3.29 J3.31 J3.33 J3.37 J3.39 J3.41 J3.42 J3.43 J3.44 J3.45 J3.46 J3.48 J3.49 J3.50 J8.1 J9.1 J10.1 J11.1 J12.1 J13.1 J14.1 J15.1 J16.1 U2.8 U2.9 U2.10 U2.12 U2.13 U2.14 U4.8 U4.9 U4.10 U4.12 U4.13 U4.14 U9.V U11.7 U17.14 U17.15 U17.V U19.14 U19.15 U19.V

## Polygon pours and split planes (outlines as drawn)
GND on Bottom Layer "Bottom Layer-AGND" (solid, remove dead copper, pour order 7): 12560,11360 12560,10630 12160,10630 12160,11360 10740,11360 10740,11790 10560,11970 3210,11970 2600,11360 1170,11360 1170,13550 13010,13550 13010,11810
C2_Neut on Bottom Layer "C2_NEUT_L04_P001" (solid, pour order 1): 7438.65,11258.89 7438.65,9758.89 8618.65,8578.89 10598.65,8578.89 10598.65,11258.42 10601.35,11261.11
C1_Neut on Bottom Layer "C1_NEUT_L04_P000" (solid, pour order 0): 7320,11250 7320,9760 6163.04,8603.04 4240,8603.04 4240,11250
-15V on Bottom Layer "-15V_L04_P004" (solid, pour order 4): 9880,11460 9880,11580 9880,12680 9660,12680 9660,11680 4640,11680 4640,12440 4420,12440 4420,11460
Earth on Bottom Layer "EARTH_L04_P008" (solid, pour order 8): 13780,11300 13780,10630 12720,10630 12720,11300
-15V on Top Layer "tga" (solid, remove dead copper, pour order 5): 7280,13290 7880,12690 9890,12690 9890,12550 7620,12550 7030,13140 4930,13140 4640,12850 4640,12350 4420,12350 4420,12900 4810,13290
+15V on Top Layer "+15V_L01_P002" (solid, pour order 2): 4760,11470 10140,11470 10140,11680 4760,11680

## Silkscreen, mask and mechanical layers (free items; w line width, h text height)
Top Overlay:
  drawing of 119 lines, arcs and shapes, not listed
  text "Inverter 2" at 6760,12830 h60
  text "Inverter 1" at 4870,12740 h60
  text "EPWM" at 7347,12737 h42
  text "1A/B" at 7347,12677 h42
  text "EPWM" at 5747,12647 h42
  text "2A/B" at 7347,12617 h42
  text "6B/A" at 5747,12587 h42
  text "3A/B" at 7347,12557 h42
  text "5B/A" at 5747,12527 h42
  text "4B/A" at 5747,12467 h42
  text "LCL1" at 2240,11220 h60
  text "LCL2" at 11040,11200 h60
  text "Isolation" at 3720,11160 h60
  text "Cf_A" at 2997,11054 h42
  text "Cf_C" at 11177,11044 h42
  text "Lf_A" at 2587,10974 h42
  text "Lf_C" at 11587,10974 h42
  text "Cf_B" at 2927,10924 h42
  text "Cf_B" at 11237,10914 h42
  text "Channels" at 1717,10867 h42
  text "Lf_B" at 2587,10824 h42
  text "Lf_B" at 11587,10824 h42
  text "L_CM" at 2337,10804 h42
  text "Cf_C" at 2857,10794 h42
  text "L_CM" at 11837,10794 h42
  text "Cf_A" at 11327,10784 h42
  text "C1" at 1967,10777 h42
  text "VC_1A" at 1707,10774 h42
  text "C2" at 1967,10717 h42
  text "VC_1B" at 1707,10714 h42
  text "Lg_C" at 2851,10693 h42 r270
  text "Lg_B" at 3001,10693 h42 r270
  text "Lg_A" at 3151,10693 h42 r270
  text "Lg_C" at 11131,10683 h42 r270
  text "Lg_B" at 11281,10683 h42 r270
  text "Lg_A" at 11441,10683 h42 r270
  text "Lf_C" at 2587,10674 h42
  text "Lf_A" at 11587,10674 h42
  text "C3" at 1967,10657 h42
  text "VC_1C" at 1707,10654 h42
  text "D1" at 1967,10597 h42
  text "IL_1A" at 1707,10594 h42
  text "D2" at 1967,10537 h42
  text "IL_1B" at 1707,10534 h42
  text "Earth" at 13360,10510 h60
  text "D3" at 1967,10477 h42
  text "IL_1C" at 1707,10474 h42
  text "D4" at 1967,10407 h42
  text "VDC_1" at 1707,10404 h42
  text "B2" at 1967,10297 h42
  text "VC_2A" at 1707,10294 h42
  text "B3" at 1967,10237 h42
  text "VC_2B" at 1707,10234 h42
  text "B4" at 1967,10177 h42
  text "VC_2C" at 1707,10174 h42
  text "A2" at 1967,10117 h42
  text "IL_2A" at 1707,10114 h42
  text "A3" at 1967,10057 h42
  text "IL_2B" at 1707,10054 h42
  text "A1" at 1967,9997 h42
  text "IL_2C" at 1707,9994 h42
  text "A4" at 1967,9927 h42
  text "VDC_2" at 1707,9924 h42
  text "A" at 13208.44,9592 h60
  text "B" at 13405.29,9592 h60
  text "C" at 13602.15,9592 h60
  text "A" at 1190,9582 h60
  text "B" at 1389,9582 h60
  text "C" at 1585.85,9582 h60
  text "BOOSTXL-3PHGANINV Interface Board" at 6662.87,9072.87 h49.21
  text "Imperial College Dept. of EEE" at 6893.94,8987.06 h39.37
  text "FYP for ytc19" at 7213.94,8897.06 h39.37
  text "Ver2.1" at 7343.94,8813.94 h39.37
  text "C B A" at 9140,6800 h60
  text "C B A" at 5400,6760 h60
